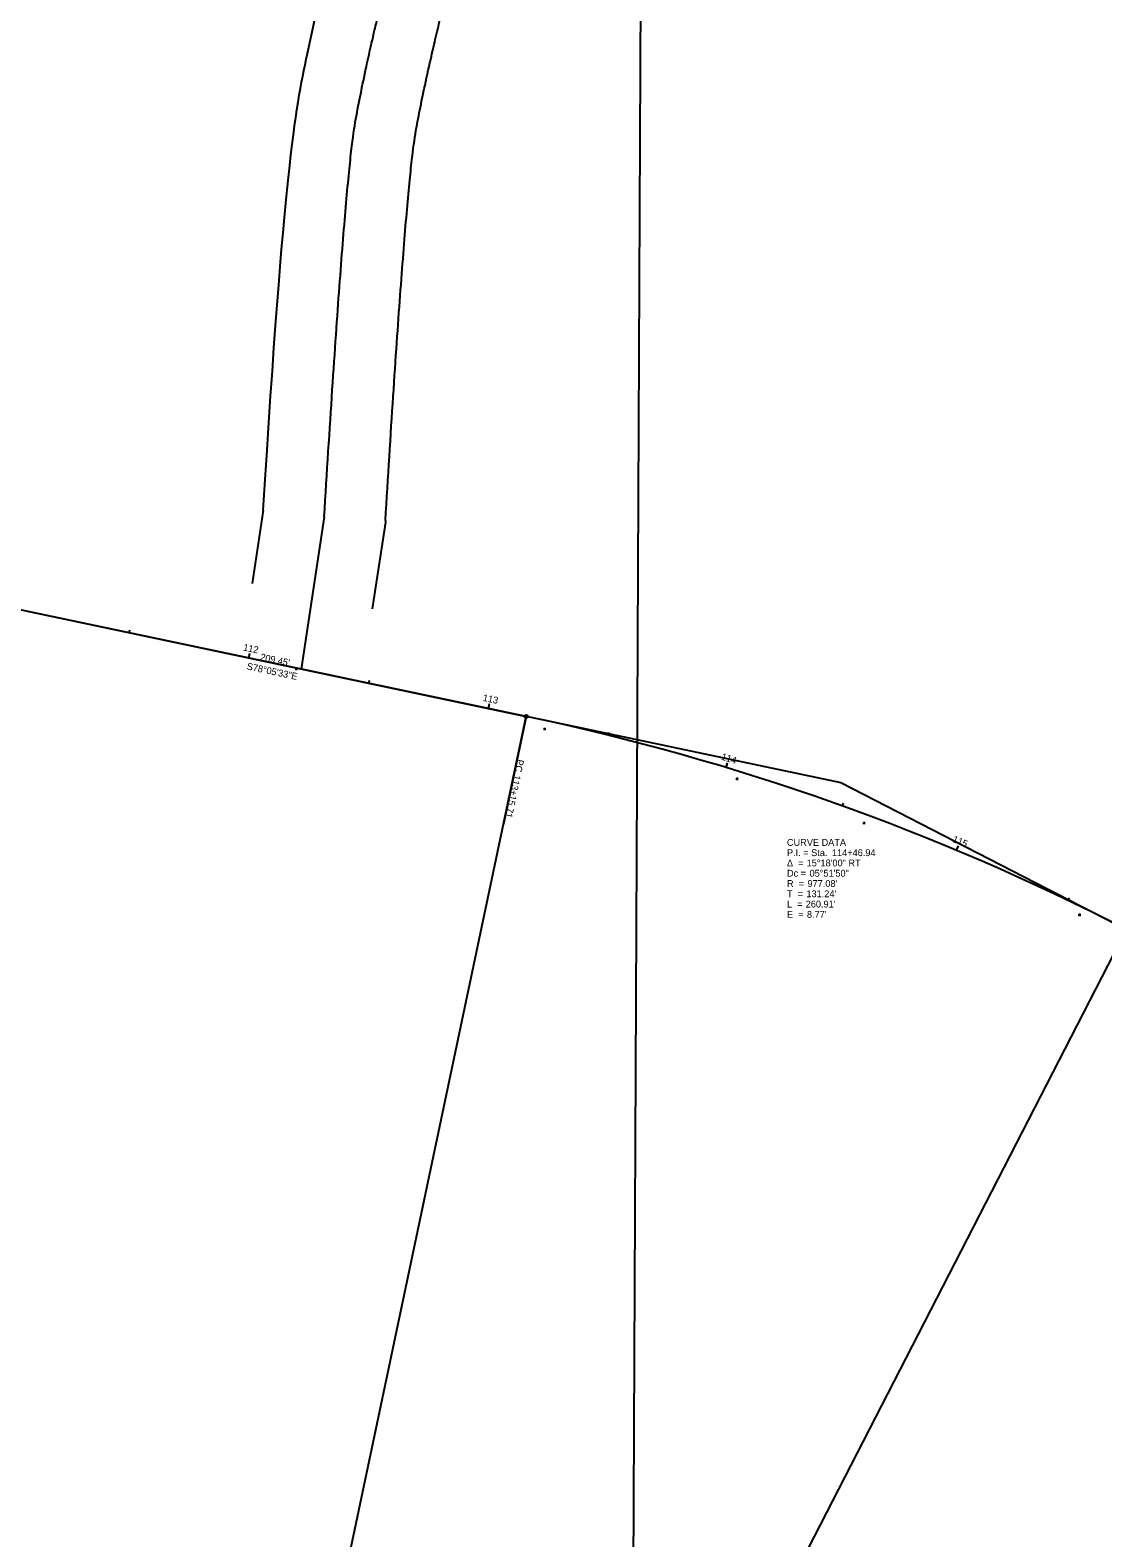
# Model space of a CAD drawing. Extents: x 2003596 to 2006933, y 570827 to 573780.
# Drawn here: x 2003884 to 2004322, y 572548 to 573164 of the extents above; entities that cross this region are included whole.
import ezdxf

# ---------------------------------------------------------------- set-up
doc = ezdxf.new("R2010")
doc.units = 0
for name, color, linetype in [('DV_X_Lot_Line', 7, 'Continuous'), ('GE_X_Alignment', 7, 'Continuous'), ('GE_X_Alignment_1000_Bearings', 7, 'Continuous'), ('GE_X_Alignment_1000_Cardinal_Points', 7, 'Continuous'), ('GE_X_Alignment_1000_Curve_Data', 7, 'Continuous'), ('GE_X_Alignment_1000_Distances', 7, 'Continuous'), ('GE_X_Alignment_1000_Stations', 7, 'Continuous'), ('GE_X_Alignment_100_Bearings', 7, 'Continuous'), ('GE_X_Alignment_100_Cardinal_Points', 7, 'Continuous'), ('GE_X_Alignment_100_Curve_Data', 7, 'Continuous'), ('GE_X_Alignment_100_Distances', 7, 'Continuous'), ('GE_X_Alignment_100_Stations', 7, 'Continuous'), ('GE_X_Alignment_500_Bearings', 7, 'Continuous'), ('GE_X_Alignment_500_Cardinal_Points', 7, 'Continuous'), ('GE_X_Alignment_500_Curve_Data', 7, 'Continuous'), ('GE_X_Alignment_500_Distances', 7, 'Continuous'), ('GE_X_Alignment_500_Stations', 7, 'Continuous'), ('RW_X_Esmt_SH', 7, 'Continuous'), ('SC_Scratch1', 7, 'Continuous'), ('SV_X_Random_Point', 7, 'Continuous'), ('SV_X_Shot_Marker', 7, 'Continuous')]:
    doc.layers.add(name, color=color, linetype=linetype)

msp = doc.modelspace()

# ---------------------------------------------------------------- linework, layer by layer
at = {"layer": 'DV_X_Lot_Line'}
msp.add_line((2004134.96, 573454.37), (2004122.72, 570849.83), dxfattribs=at)
at = {"layer": 'GE_X_Alignment'}
for p, q in [((2004004.46, 572965.58), (2003994.98, 572903.3)), ((2003882.01, 572927.27), (2004086.95, 572884.06))]:
    msp.add_line(p, q, dxfattribs=at)
msp.add_arc((2003885.35, 571928), 977.08, 62.79264, 78.09264, dxfattribs=at)
msp.add_open_spline([(2004004.46, 572965.58), (2004012.9, 573103.07), (2004021.33, 573150.19), (2004038.2, 573217.7), (2004071.23, 573301.39), (2004097.94, 573362.23), (2004116.22, 573410.05), (2004127.11, 573446.97), (2004132.03, 573477.57), (2004136.6, 573518.01), (2004135.4, 573600.6), (2004129.26, 573779.51)], degree=2, dxfattribs=at)
at = {"layer": 'GE_X_Alignment_1000_Bearings'}
msp.add_line((2004029.42, 572964.04), (2004029.42, 572963.38), dxfattribs=at)
at = {"layer": 'GE_X_Alignment_1000_Cardinal_Points'}
msp.add_line((2004086.95, 572884.06), (2004077.67, 572840.02), dxfattribs=at)
msp.add_circle((2004086.95, 572884.06), 0.6, dxfattribs=at)
at = {"layer": 'GE_X_Alignment_1000_Stations'}
msp.add_line((2004262.64, 572829.3), (2004263.1, 572830.41), dxfattribs=at)
at = {"layer": 'GE_X_Alignment_100_Cardinal_Points'}
msp.add_line((2004086.95, 572884.06), (2004077.67, 572840.02), dxfattribs=at)
msp.add_circle((2004086.95, 572884.06), 0.6, dxfattribs=at)
at = {"layer": 'GE_X_Alignment_100_Stations'}
for p, q in [((2003924.81, 572918.25), (2003925.06, 572919.42)), ((2003973.74, 572907.93), (2003974.15, 572909.89)), ((2004022.66, 572897.61), (2004022.91, 572898.79)), ((2004071.58, 572887.3), (2004072, 572889.25)), ((2004120.38, 572876.39), (2004120.67, 572877.56)), ((2004168.58, 572863.13), (2004169.16, 572865.04)), ((2004216.04, 572847.42), (2004216.45, 572848.55)), ((2004262.64, 572829.3), (2004263.41, 572831.14)), ((2004308.25, 572808.82), (2004308.77, 572809.9))]:
    msp.add_line(p, q, dxfattribs=at)
at = {"layer": 'GE_X_Alignment_500_Cardinal_Points'}
msp.add_line((2004086.95, 572884.06), (2004077.67, 572840.02), dxfattribs=at)
msp.add_circle((2004086.95, 572884.06), 0.6, dxfattribs=at)
at = {"layer": 'GE_X_Alignment_500_Stations'}
for p, q in [((2003973.74, 572907.93), (2003973.98, 572909.1)), ((2004071.58, 572887.3), (2004071.83, 572888.47)), ((2004168.58, 572863.13), (2004168.93, 572864.28)), ((2004262.64, 572829.3), (2004263.41, 572831.14))]:
    msp.add_line(p, q, dxfattribs=at)
at = {"layer": 'RW_X_Esmt_SH'}
for p, q in [((2003979.58, 572968.23), (2003975.02, 572938.32)), ((2004029.42, 572963.38), (2004024.03, 572927.98))]:
    msp.add_line(p, q, dxfattribs=at)
for points, degree in [([(2003979.58, 572968.23), (2003988.06, 573106.18), (2003996.89, 573155.49), (2004014.34, 573225.36), (2004048.15, 573311.01), (2004074.81, 573371.72), (2004092.51, 573418.06), (2004102.68, 573452.52), (2004107.25, 573480.96), (2004111.58, 573519.23), (2004110.41, 573599.99), (2004104.28, 573778.66)], 3), ([(2004029.42, 572964.04), (2004037.76, 573100.09), (2004045.79, 573144.95), (2004062.06, 573210.05), (2004094.31, 573291.78), (2004121.08, 573352.74), (2004139.92, 573402.04), (2004151.54, 573441.43), (2004156.81, 573474.18), (2004161.62, 573516.78), (2004160.39, 573601.21), (2004154.25, 573780.37)], 2)]:
    msp.add_open_spline(points, degree=degree, dxfattribs=at)
at = {"layer": 'SC_Scratch1'}
for p, q in [((2003794.54, 572945.72), (2004215.36, 572856.98)), ((2003885.35, 571928), (2004086.95, 572884.06)), ((2004215.36, 572856.98), (2004332.08, 572796.97)), ((2003885.35, 571928), (2004332.08, 572796.97))]:
    msp.add_line(p, q, dxfattribs=at)
at = {"layer": 'SV_X_Random_Point'}
for p, q in [((2004086.29, 572883.39), (2004087.62, 572884.72)), ((2004086.29, 572884.72), (2004087.62, 572883.39))]:
    msp.add_line(p, q, dxfattribs=at)
at = {"layer": 'SV_X_Shot_Marker'}
for p, q in [((2003992.57, 572903.41), (2003993.57, 572903.41)), ((2003993.07, 572903.91), (2003993.07, 572902.91)), ((2003993.07, 572903.41), (2003993.07, 572903.41)), ((2004093.93, 572878.92), (2004094.93, 572878.92)), ((2004094.43, 572879.42), (2004094.43, 572878.42)), ((2004094.43, 572878.92), (2004094.43, 572878.92)), ((2004172.52, 572858.53), (2004173.52, 572858.53)), ((2004173.02, 572859.03), (2004173.02, 572858.03)), ((2004173.02, 572858.53), (2004173.02, 572858.53)), ((2004224.88, 572840.98), (2004224.88, 572839.98)), ((2004224.38, 572840.48), (2004225.38, 572840.48)), ((2004224.88, 572840.48), (2004224.88, 572840.48)), ((2004312.33, 572802.99), (2004313.33, 572802.99)), ((2004312.83, 572803.49), (2004312.83, 572802.49)), ((2004312.83, 572802.99), (2004312.83, 572802.99))]:
    msp.add_line(p, q, dxfattribs=at)

# ---------------------------------------------------------------- texts
at = {"layer": 'GE_X_Alignment_1000_Bearings'}
msp.add_text('S78°05\'33"E', height=2.8, rotation=348.09252, dxfattribs=at).set_placement((2003972.65, 572903.25))
at = {"layer": 'GE_X_Alignment_1000_Cardinal_Points'}
for s, p in [('PC', (2004083.34, 572866.69)), ('113+15.71', (2004081.99, 572860.31))]:
    msp.add_text(s, height=2.8, rotation=258.09264, dxfattribs=at).set_placement(p)
at = {"layer": 'GE_X_Alignment_1000_Curve_Data'}
for s, p in [('CURVE DATA', (2004193.4, 572831.16)), ('P.I. = Sta. ', (2004193.4, 572826.96)), ('114+46.94', (2004211.77, 572826.96)), ('Δ  = ', (2004193.4, 572822.76)), ('15°18\'00" RT', (2004201.43, 572822.76)), ('Dc = ', (2004193.4, 572818.56)), ('R  = ', (2004193.4, 572814.36)), ("977.08'", (2004201.77, 572814.36)), ('05°51\'50"', (2004202.64, 572818.56)), ('T  = ', (2004193.4, 572810.16)), ("131.24'", (2004201.34, 572810.16)), ('L  = ', (2004193.4, 572805.96)), ('E  = ', (2004193.4, 572801.76)), ("260.91'", (2004201.05, 572805.96)), ("8.77'", (2004201.56, 572801.76))]:
    msp.add_text(s, height=2.8, dxfattribs=at).set_placement(p)
at = {"layer": 'GE_X_Alignment_1000_Distances'}
msp.add_text("209.45'", height=2.8, rotation=348.09252, dxfattribs=at).set_placement((2003978.14, 572907.05))
at = {"layer": 'GE_X_Alignment_100_Bearings'}
msp.add_text('S78°05\'33"E', height=2.8, rotation=348.09252, dxfattribs=at).set_placement((2003972.65, 572903.25))
at = {"layer": 'GE_X_Alignment_100_Cardinal_Points'}
for s, p in [('PC', (2004083.34, 572866.69)), ('113+15.71', (2004081.99, 572860.31))]:
    msp.add_text(s, height=2.8, rotation=258.09264, dxfattribs=at).set_placement(p)
at = {"layer": 'GE_X_Alignment_100_Curve_Data'}
for s, p in [('CURVE DATA', (2004193.4, 572831.16)), ('P.I. = Sta. ', (2004193.4, 572826.96)), ('114+46.94', (2004211.77, 572826.96)), ('Δ  = ', (2004193.4, 572822.76)), ('15°18\'00" RT', (2004201.43, 572822.76)), ('Dc = ', (2004193.4, 572818.56)), ('R  = ', (2004193.4, 572814.36)), ("977.08'", (2004201.77, 572814.36)), ('05°51\'50"', (2004202.64, 572818.56)), ('T  = ', (2004193.4, 572810.16)), ("131.24'", (2004201.34, 572810.16)), ('L  = ', (2004193.4, 572805.96)), ('E  = ', (2004193.4, 572801.76)), ("260.91'", (2004201.05, 572805.96)), ("8.77'", (2004201.56, 572801.76))]:
    msp.add_text(s, height=2.8, dxfattribs=at).set_placement(p)
at = {"layer": 'GE_X_Alignment_100_Distances'}
msp.add_text("209.45'", height=2.8, rotation=348.09252, dxfattribs=at).set_placement((2003978.14, 572907.05))
at = {"layer": 'GE_X_Alignment_100_Stations'}
for s, rotation, p in [('112', 348.09252, (2003971.19, 572911.02)), ('113', 348.09252, (2004069.06, 572890.43)), ('114', 343.14962, (2004166.34, 572866.42)), ('115', 337.28564, (2004260.72, 572832.86))]:
    msp.add_text(s, height=2.8, rotation=rotation, dxfattribs=at).set_placement(p)
at = {"layer": 'GE_X_Alignment_500_Bearings'}
msp.add_text('S78°05\'33"E', height=2.8, rotation=348.09252, dxfattribs=at).set_placement((2003972.65, 572903.25))
at = {"layer": 'GE_X_Alignment_500_Cardinal_Points'}
for s, p in [('PC', (2004083.34, 572866.69)), ('113+15.71', (2004081.99, 572860.31))]:
    msp.add_text(s, height=2.8, rotation=258.09264, dxfattribs=at).set_placement(p)
at = {"layer": 'GE_X_Alignment_500_Curve_Data'}
for s, p in [('CURVE DATA', (2004193.4, 572831.16)), ('P.I. = Sta. ', (2004193.4, 572826.96)), ('114+46.94', (2004211.77, 572826.96)), ('Δ  = ', (2004193.4, 572822.76)), ('15°18\'00" RT', (2004201.43, 572822.76)), ('Dc = ', (2004193.4, 572818.56)), ('R  = ', (2004193.4, 572814.36)), ("977.08'", (2004201.77, 572814.36)), ('05°51\'50"', (2004202.64, 572818.56)), ('T  = ', (2004193.4, 572810.16)), ("131.24'", (2004201.34, 572810.16)), ('L  = ', (2004193.4, 572805.96)), ('E  = ', (2004193.4, 572801.76)), ("260.91'", (2004201.05, 572805.96)), ("8.77'", (2004201.56, 572801.76))]:
    msp.add_text(s, height=2.8, dxfattribs=at).set_placement(p)
at = {"layer": 'GE_X_Alignment_500_Distances'}
msp.add_text("209.45'", height=2.8, rotation=348.09252, dxfattribs=at).set_placement((2003978.14, 572907.05))
at = {"layer": 'GE_X_Alignment_500_Stations'}
msp.add_text('115', height=2.8, rotation=337.28564, dxfattribs=at).set_placement((2004260.72, 572832.86))

doc.saveas('drawing.dxf')
